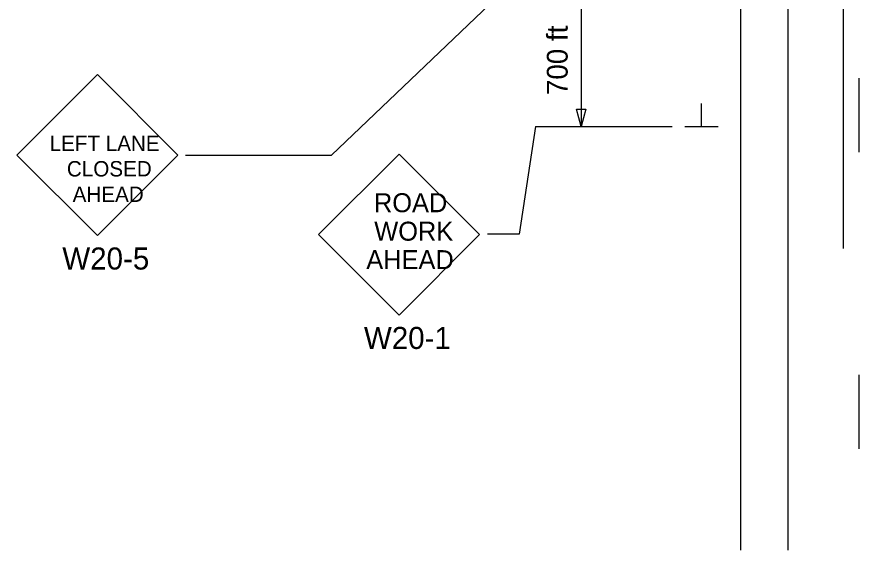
# Model space of a CAD drawing. Extents: x 15278 to 18126, y 1908 to 6555.
# Drawn here: x 16332.4 to 16616.4, y 2305.6 to 2485.4 of the extents above; entities that cross this region are included whole.
import ezdxf

# ---------------------------------------------------------------- set-up
doc = ezdxf.new("R2010")
doc.units = 0
for name, color, linetype in [('ALI_LEGAL_EX', 7, 'Continuous'), ('Level 3', 7, 'Continuous'), ('PAVT_EDGE_EX', 7, 'Continuous'), ('TRAFFIC_SIGNS_PR', 7, 'Continuous'), ('TYPICAL_TEXT_DIMEN_PR', 7, 'Continuous')]:
    doc.layers.add(name, color=color, linetype=linetype)

msp = doc.modelspace()

# ---------------------------------------------------------------- linework, layer by layer
at = {"layer": 'ALI_LEGAL_EX'}
msp.add_line((16610.98, 3236.46), (16610.98, 2407.28), dxfattribs=at)
for points in [[(16616.35, 2439.74), (16616.35, 2464.74)], [(16616.35, 2339.74), (16616.35, 2364.74)]]:
    msp.add_lwpolyline(points, dxfattribs=at)
at = {"layer": 'Level 3'}
msp.add_line((16501.79, 2412.13), (16491.04, 2412.13), dxfattribs=at)
at = {"layer": 'PAVT_EDGE_EX'}
for p, q in [((16576.35, 3138.78), (16576.35, 2305.55)), ((16592.35, 3138.78), (16592.35, 2305.55))]:
    msp.add_line(p, q, dxfattribs=at)
at = {"layer": 'TRAFFIC_SIGNS_PR'}
for p, q in [((16359.59, 2465.95), (16332.44, 2438.8)), ((16386.75, 2438.8), (16359.59, 2465.95)), ((16332.44, 2438.8), (16359.59, 2411.64)), ((16359.59, 2411.64), (16386.75, 2438.8)), ((16461.26, 2439.15), (16434.1, 2412)), ((16488.41, 2412), (16461.26, 2439.15)), ((16434.1, 2412), (16461.26, 2384.85)), ((16461.26, 2384.85), (16488.41, 2412))]:
    msp.add_line(p, q, dxfattribs=at)
at = {"layer": 'TYPICAL_TEXT_DIMEN_PR'}
for p, q in [((16500.94, 2498.48), (16438.49, 2438.78)), ((16522.62, 2498.48), (16522.62, 2448.48)), ((16563.23, 2448.48), (16563.23, 2456.26)), ((16522.62, 2448.48), (16521.05, 2454.34)), ((16521.05, 2454.34), (16522.62, 2454.34)), ((16522.62, 2454.34), (16524.2, 2454.34)), ((16524.2, 2454.34), (16522.62, 2448.48)), ((16507.25, 2448.48), (16501.79, 2412.13)), ((16507.25, 2448.48), (16553.35, 2448.48)), ((16557.6, 2448.48), (16568.85, 2448.48)), ((16389.31, 2438.78), (16438.49, 2438.78))]:
    msp.add_line(p, q, dxfattribs=at)

# ---------------------------------------------------------------- texts
at = {"layer": 'TRAFFIC_SIGNS_PR'}
for s, height, p in [('LEFT LANE', 5.2, (16343.47, 2440.19)), ('CLOSED', 5.2, (16349.31, 2431.59)), ('AHEAD', 5.2, (16351.25, 2422.99)), ('ROAD', 6.4, (16452.8, 2419.54)), ('WORK', 6.4, (16452.91, 2409.94)), ('W20-5', 7.44, (16347.77, 2400.2)), ('AHEAD', 6.4, (16450.22, 2400.34)), ('W20-1', 7.44, (16449.43, 2373.41))]:
    msp.add_text(s, height=height, dxfattribs=at).set_placement(p)
at = {"layer": 'TYPICAL_TEXT_DIMEN_PR'}
msp.add_text('700 ft', height=7, rotation=90, dxfattribs=at).set_placement((16518.1, 2459.05))

doc.saveas('drawing.dxf')
